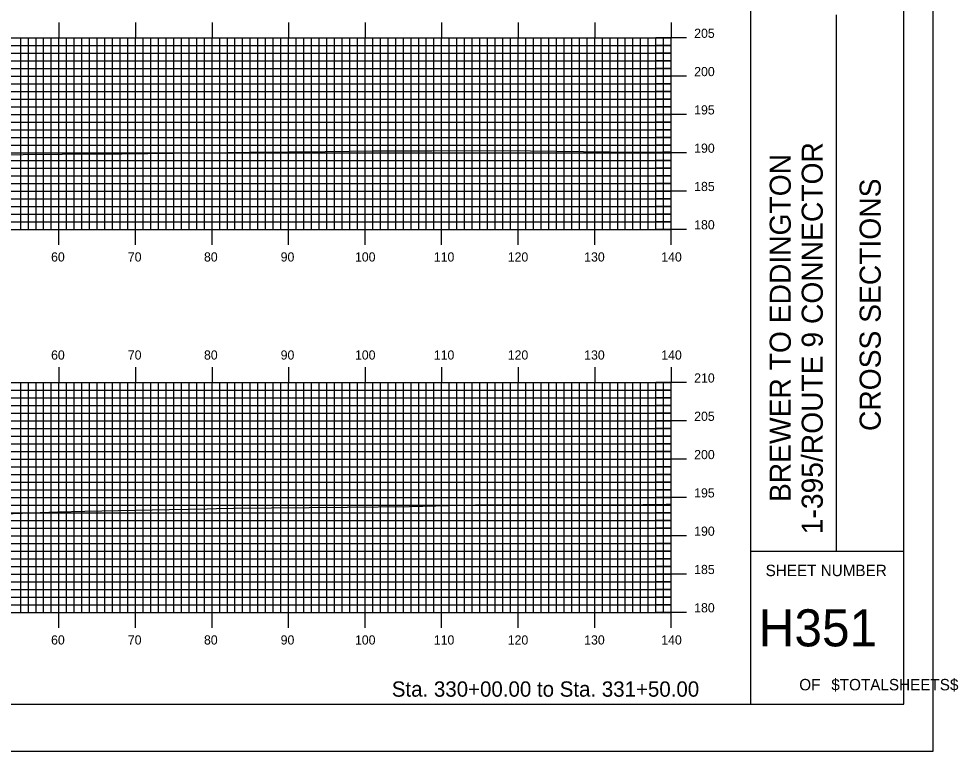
# Model space of a CAD drawing. Extents: x 1822392 to 1822735, y 442591 to 442811.
# Drawn here: x 1822612.5 to 1822735.3, y 442590.5 to 442686.2 of the extents above; entities that cross this region are included whole.
import ezdxf

# ---------------------------------------------------------------- set-up
doc = ezdxf.new("R2010")
doc.units = 0
for name, color, linetype in [('BORDER', 7, 'Continuous'), ('H_V ANNOTATION', 7, 'Continuous'), ('MAJOR', 7, 'Continuous'), ('MINOR', 7, 'Continuous'), ('PLOT BOUNDARY', 7, 'Continuous'), ('S_Roadway_Centerline', 7, 'Continuous')]:
    doc.layers.add(name, color=color, linetype=linetype)

msp = doc.modelspace()

# ---------------------------------------------------------------- linework, layer by layer
at = {"layer": 'BORDER'}
for p, q in [((1822708.17, 442596.67), (1822708.17, 442806.67)), ((1822719.35, 442616.67), (1822719.35, 442686.67)), ((1822708.17, 442616.67), (1822728.17, 442616.67))]:
    msp.add_line(p, q, dxfattribs=at)
msp.add_lwpolyline([(1822408.17, 442596.67), (1822728.17, 442596.67), (1822728.17, 442806.67), (1822408.17, 442806.67)], close=True, dxfattribs=at)
at = {"layer": 'MAJOR'}
for p, q in [((1822617.77, 442685.67), (1822617.77, 442683.67)), ((1822627.77, 442685.67), (1822627.77, 442683.67)), ((1822637.77, 442685.67), (1822637.77, 442683.67)), ((1822647.77, 442685.67), (1822647.77, 442683.67)), ((1822657.77, 442685.67), (1822657.77, 442683.67)), ((1822667.77, 442685.67), (1822667.77, 442683.67)), ((1822677.77, 442685.67), (1822677.77, 442683.67)), ((1822687.77, 442685.67), (1822687.77, 442683.67)), ((1822697.77, 442685.67), (1822697.77, 442683.67)), ((1822417.77, 442683.67), (1822697.77, 442683.67)), ((1822417.77, 442683.67), (1822697.77, 442683.67)), ((1822617.77, 442658.67), (1822617.77, 442683.67)), ((1822627.77, 442658.67), (1822627.77, 442683.67)), ((1822637.77, 442658.67), (1822637.77, 442683.67)), ((1822647.77, 442658.67), (1822647.77, 442683.67)), ((1822657.77, 442658.67), (1822657.77, 442683.67)), ((1822667.77, 442658.67), (1822667.77, 442683.67)), ((1822677.77, 442658.67), (1822677.77, 442683.67)), ((1822687.77, 442658.67), (1822687.77, 442683.67)), ((1822699.77, 442683.67), (1822695.77, 442683.67)), ((1822697.77, 442658.67), (1822697.77, 442683.67)), ((1822697.77, 442658.67), (1822697.77, 442683.67)), ((1822417.77, 442678.67), (1822697.77, 442678.67)), ((1822699.77, 442678.67), (1822695.77, 442678.67)), ((1822417.77, 442673.67), (1822697.77, 442673.67)), ((1822699.77, 442673.67), (1822695.77, 442673.67)), ((1822417.77, 442668.67), (1822697.77, 442668.67)), ((1822699.77, 442668.67), (1822695.77, 442668.67)), ((1822417.77, 442663.67), (1822697.77, 442663.67)), ((1822699.77, 442663.67), (1822695.77, 442663.67)), ((1822417.77, 442658.67), (1822697.77, 442658.67)), ((1822417.77, 442658.67), (1822697.77, 442658.67)), ((1822617.77, 442656.66), (1822617.77, 442658.67)), ((1822627.77, 442656.66), (1822627.77, 442658.67)), ((1822637.77, 442656.66), (1822637.77, 442658.67)), ((1822647.77, 442656.66), (1822647.77, 442658.67)), ((1822657.77, 442656.66), (1822657.77, 442658.67)), ((1822667.77, 442656.66), (1822667.77, 442658.67)), ((1822677.77, 442656.66), (1822677.77, 442658.67)), ((1822687.77, 442656.66), (1822687.77, 442658.67)), ((1822699.77, 442658.67), (1822695.77, 442658.67)), ((1822697.77, 442656.66), (1822697.77, 442658.67)), ((1822617.77, 442640.67), (1822617.77, 442638.67)), ((1822627.77, 442640.67), (1822627.77, 442638.67)), ((1822637.77, 442640.67), (1822637.77, 442638.67)), ((1822647.77, 442640.67), (1822647.77, 442638.67)), ((1822657.77, 442640.67), (1822657.77, 442638.67)), ((1822667.77, 442640.67), (1822667.77, 442638.67)), ((1822677.77, 442640.67), (1822677.77, 442638.67)), ((1822687.77, 442640.67), (1822687.77, 442638.67)), ((1822697.77, 442640.67), (1822697.77, 442638.67)), ((1822417.77, 442638.67), (1822697.77, 442638.67)), ((1822417.77, 442638.67), (1822697.77, 442638.67)), ((1822617.77, 442608.67), (1822617.77, 442638.67)), ((1822627.77, 442608.67), (1822627.77, 442638.67)), ((1822637.77, 442608.67), (1822637.77, 442638.67)), ((1822647.77, 442608.67), (1822647.77, 442638.67)), ((1822657.77, 442608.67), (1822657.77, 442638.67)), ((1822667.77, 442608.67), (1822667.77, 442638.67)), ((1822677.77, 442608.67), (1822677.77, 442638.67)), ((1822687.77, 442608.67), (1822687.77, 442638.67)), ((1822699.77, 442638.67), (1822695.77, 442638.67)), ((1822697.77, 442608.67), (1822697.77, 442638.67)), ((1822697.77, 442608.67), (1822697.77, 442638.67)), ((1822417.77, 442633.67), (1822697.77, 442633.67)), ((1822699.77, 442633.67), (1822695.77, 442633.67)), ((1822417.77, 442628.67), (1822697.77, 442628.67)), ((1822699.77, 442628.67), (1822695.77, 442628.67)), ((1822417.77, 442623.67), (1822697.77, 442623.67)), ((1822699.77, 442623.67), (1822695.77, 442623.67)), ((1822417.77, 442618.67), (1822697.77, 442618.67)), ((1822699.77, 442618.67), (1822695.77, 442618.67)), ((1822417.77, 442613.67), (1822697.77, 442613.67)), ((1822699.77, 442613.67), (1822695.77, 442613.67)), ((1822417.77, 442608.67), (1822697.77, 442608.67)), ((1822417.77, 442608.67), (1822697.77, 442608.67)), ((1822617.77, 442606.66), (1822617.77, 442608.67)), ((1822627.77, 442606.66), (1822627.77, 442608.67)), ((1822637.77, 442606.66), (1822637.77, 442608.67)), ((1822647.77, 442606.66), (1822647.77, 442608.67)), ((1822657.77, 442606.66), (1822657.77, 442608.67)), ((1822667.77, 442606.66), (1822667.77, 442608.67)), ((1822677.77, 442606.66), (1822677.77, 442608.67)), ((1822687.77, 442606.66), (1822687.77, 442608.67)), ((1822699.77, 442608.67), (1822695.77, 442608.67)), ((1822697.77, 442606.66), (1822697.77, 442608.67))]:
    msp.add_line(p, q, dxfattribs=at)
at = {"layer": 'MINOR'}
for p, q in [((1822612.77, 442658.67), (1822612.77, 442683.67)), ((1822613.77, 442658.67), (1822613.77, 442683.67)), ((1822614.77, 442658.67), (1822614.77, 442683.67)), ((1822615.77, 442658.67), (1822615.77, 442683.67)), ((1822616.77, 442658.67), (1822616.77, 442683.67)), ((1822618.77, 442658.67), (1822618.77, 442683.67)), ((1822619.77, 442658.67), (1822619.77, 442683.67)), ((1822620.77, 442658.67), (1822620.77, 442683.67)), ((1822621.77, 442658.67), (1822621.77, 442683.67)), ((1822622.77, 442658.67), (1822622.77, 442683.67)), ((1822623.77, 442658.67), (1822623.77, 442683.67)), ((1822624.77, 442658.67), (1822624.77, 442683.67)), ((1822625.77, 442658.67), (1822625.77, 442683.67)), ((1822626.77, 442658.67), (1822626.77, 442683.67)), ((1822628.77, 442658.67), (1822628.77, 442683.67)), ((1822629.77, 442658.67), (1822629.77, 442683.67)), ((1822630.77, 442658.67), (1822630.77, 442683.67)), ((1822631.77, 442658.67), (1822631.77, 442683.67)), ((1822632.77, 442658.67), (1822632.77, 442683.67)), ((1822633.77, 442658.67), (1822633.77, 442683.67)), ((1822634.77, 442658.67), (1822634.77, 442683.67)), ((1822635.77, 442658.67), (1822635.77, 442683.67)), ((1822636.77, 442658.67), (1822636.77, 442683.67)), ((1822638.77, 442658.67), (1822638.77, 442683.67)), ((1822639.77, 442658.67), (1822639.77, 442683.67)), ((1822640.77, 442658.67), (1822640.77, 442683.67)), ((1822641.77, 442658.67), (1822641.77, 442683.67)), ((1822642.77, 442658.67), (1822642.77, 442683.67)), ((1822643.77, 442658.67), (1822643.77, 442683.67)), ((1822644.77, 442658.67), (1822644.77, 442683.67)), ((1822645.77, 442658.67), (1822645.77, 442683.67)), ((1822646.77, 442658.67), (1822646.77, 442683.67)), ((1822648.77, 442658.67), (1822648.77, 442683.67)), ((1822649.77, 442658.67), (1822649.77, 442683.67)), ((1822650.77, 442658.67), (1822650.77, 442683.67)), ((1822651.77, 442658.67), (1822651.77, 442683.67)), ((1822652.77, 442658.67), (1822652.77, 442683.67)), ((1822653.77, 442658.67), (1822653.77, 442683.67)), ((1822654.77, 442658.67), (1822654.77, 442683.67)), ((1822655.77, 442658.67), (1822655.77, 442683.67)), ((1822656.77, 442658.67), (1822656.77, 442683.67)), ((1822658.77, 442658.67), (1822658.77, 442683.67)), ((1822659.77, 442658.67), (1822659.77, 442683.67)), ((1822660.77, 442658.67), (1822660.77, 442683.67)), ((1822661.77, 442658.67), (1822661.77, 442683.67)), ((1822662.77, 442658.67), (1822662.77, 442683.67)), ((1822663.77, 442658.67), (1822663.77, 442683.67)), ((1822664.77, 442658.67), (1822664.77, 442683.67)), ((1822665.77, 442658.67), (1822665.77, 442683.67)), ((1822666.77, 442658.67), (1822666.77, 442683.67)), ((1822668.77, 442658.67), (1822668.77, 442683.67)), ((1822669.77, 442658.67), (1822669.77, 442683.67)), ((1822670.77, 442658.67), (1822670.77, 442683.67)), ((1822671.77, 442658.67), (1822671.77, 442683.67)), ((1822672.77, 442658.67), (1822672.77, 442683.67)), ((1822673.77, 442658.67), (1822673.77, 442683.67)), ((1822674.77, 442658.67), (1822674.77, 442683.67)), ((1822675.77, 442658.67), (1822675.77, 442683.67)), ((1822676.77, 442658.67), (1822676.77, 442683.67)), ((1822678.77, 442658.67), (1822678.77, 442683.67)), ((1822679.77, 442658.67), (1822679.77, 442683.67)), ((1822680.77, 442658.67), (1822680.77, 442683.67)), ((1822681.77, 442658.67), (1822681.77, 442683.67)), ((1822682.77, 442658.67), (1822682.77, 442683.67)), ((1822683.77, 442658.67), (1822683.77, 442683.67)), ((1822684.77, 442658.67), (1822684.77, 442683.67)), ((1822685.77, 442658.67), (1822685.77, 442683.67)), ((1822686.77, 442658.67), (1822686.77, 442683.67)), ((1822688.77, 442658.67), (1822688.77, 442683.67)), ((1822689.77, 442658.67), (1822689.77, 442683.67)), ((1822690.77, 442658.67), (1822690.77, 442683.67)), ((1822691.77, 442658.67), (1822691.77, 442683.67)), ((1822692.77, 442658.67), (1822692.77, 442683.67)), ((1822693.77, 442658.67), (1822693.77, 442683.67)), ((1822694.77, 442658.67), (1822694.77, 442683.67)), ((1822695.77, 442658.67), (1822695.77, 442683.67)), ((1822696.77, 442658.67), (1822696.77, 442683.67)), ((1822417.77, 442682.67), (1822697.77, 442682.67)), ((1822417.77, 442681.67), (1822697.77, 442681.67)), ((1822697.77, 442682.67), (1822695.77, 442682.67)), ((1822697.77, 442681.67), (1822695.77, 442681.67)), ((1822417.77, 442680.67), (1822697.77, 442680.67)), ((1822697.77, 442680.67), (1822695.77, 442680.67)), ((1822417.77, 442679.67), (1822697.77, 442679.67)), ((1822697.77, 442679.67), (1822695.77, 442679.67)), ((1822417.77, 442677.67), (1822697.77, 442677.67)), ((1822417.77, 442676.67), (1822697.77, 442676.67)), ((1822697.77, 442677.67), (1822695.77, 442677.67)), ((1822697.77, 442676.67), (1822695.77, 442676.67)), ((1822417.77, 442675.67), (1822697.77, 442675.67)), ((1822697.77, 442675.67), (1822695.77, 442675.67)), ((1822417.77, 442674.67), (1822697.77, 442674.67)), ((1822697.77, 442674.67), (1822695.77, 442674.67)), ((1822417.77, 442672.67), (1822697.77, 442672.67)), ((1822697.77, 442672.67), (1822695.77, 442672.67)), ((1822417.77, 442671.67), (1822697.77, 442671.67)), ((1822417.77, 442670.67), (1822697.77, 442670.67)), ((1822697.77, 442671.67), (1822695.77, 442671.67)), ((1822697.77, 442670.67), (1822695.77, 442670.67)), ((1822417.77, 442669.67), (1822697.77, 442669.67)), ((1822697.77, 442669.67), (1822695.77, 442669.67)), ((1822417.77, 442667.67), (1822697.77, 442667.67)), ((1822697.77, 442667.67), (1822695.77, 442667.67)), ((1822417.77, 442666.67), (1822697.77, 442666.67)), ((1822417.77, 442665.67), (1822697.77, 442665.67)), ((1822697.77, 442666.67), (1822695.77, 442666.67)), ((1822697.77, 442665.67), (1822695.77, 442665.67)), ((1822417.77, 442664.67), (1822697.77, 442664.67)), ((1822697.77, 442664.67), (1822695.77, 442664.67)), ((1822417.77, 442662.67), (1822697.77, 442662.67)), ((1822697.77, 442662.67), (1822695.77, 442662.67)), ((1822417.77, 442661.67), (1822697.77, 442661.67)), ((1822417.77, 442660.67), (1822697.77, 442660.67)), ((1822697.77, 442661.67), (1822695.77, 442661.67)), ((1822697.77, 442660.67), (1822695.77, 442660.67)), ((1822417.77, 442659.67), (1822697.77, 442659.67)), ((1822697.77, 442659.67), (1822695.77, 442659.67)), ((1822612.77, 442608.67), (1822612.77, 442638.67)), ((1822613.77, 442608.67), (1822613.77, 442638.67)), ((1822614.77, 442608.67), (1822614.77, 442638.67)), ((1822615.77, 442608.67), (1822615.77, 442638.67)), ((1822616.77, 442608.67), (1822616.77, 442638.67)), ((1822618.77, 442608.67), (1822618.77, 442638.67)), ((1822619.77, 442608.67), (1822619.77, 442638.67)), ((1822620.77, 442608.67), (1822620.77, 442638.67)), ((1822621.77, 442608.67), (1822621.77, 442638.67)), ((1822622.77, 442608.67), (1822622.77, 442638.67)), ((1822623.77, 442608.67), (1822623.77, 442638.67)), ((1822624.77, 442608.67), (1822624.77, 442638.67)), ((1822625.77, 442608.67), (1822625.77, 442638.67)), ((1822626.77, 442608.67), (1822626.77, 442638.67)), ((1822628.77, 442608.67), (1822628.77, 442638.67)), ((1822629.77, 442608.67), (1822629.77, 442638.67)), ((1822630.77, 442608.67), (1822630.77, 442638.67)), ((1822631.77, 442608.67), (1822631.77, 442638.67)), ((1822632.77, 442608.67), (1822632.77, 442638.67)), ((1822633.77, 442608.67), (1822633.77, 442638.67)), ((1822634.77, 442608.67), (1822634.77, 442638.67)), ((1822635.77, 442608.67), (1822635.77, 442638.67)), ((1822636.77, 442608.67), (1822636.77, 442638.67)), ((1822638.77, 442608.67), (1822638.77, 442638.67)), ((1822639.77, 442608.67), (1822639.77, 442638.67)), ((1822640.77, 442608.67), (1822640.77, 442638.67)), ((1822641.77, 442608.67), (1822641.77, 442638.67)), ((1822642.77, 442608.67), (1822642.77, 442638.67)), ((1822643.77, 442608.67), (1822643.77, 442638.67)), ((1822644.77, 442608.67), (1822644.77, 442638.67)), ((1822645.77, 442608.67), (1822645.77, 442638.67)), ((1822646.77, 442608.67), (1822646.77, 442638.67)), ((1822648.77, 442608.67), (1822648.77, 442638.67)), ((1822649.77, 442608.67), (1822649.77, 442638.67)), ((1822650.77, 442608.67), (1822650.77, 442638.67)), ((1822651.77, 442608.67), (1822651.77, 442638.67)), ((1822652.77, 442608.67), (1822652.77, 442638.67)), ((1822653.77, 442608.67), (1822653.77, 442638.67)), ((1822654.77, 442608.67), (1822654.77, 442638.67)), ((1822655.77, 442608.67), (1822655.77, 442638.67)), ((1822656.77, 442608.67), (1822656.77, 442638.67)), ((1822658.77, 442608.67), (1822658.77, 442638.67)), ((1822659.77, 442608.67), (1822659.77, 442638.67)), ((1822660.77, 442608.67), (1822660.77, 442638.67)), ((1822661.77, 442608.67), (1822661.77, 442638.67)), ((1822662.77, 442608.67), (1822662.77, 442638.67)), ((1822663.77, 442608.67), (1822663.77, 442638.67)), ((1822664.77, 442608.67), (1822664.77, 442638.67)), ((1822665.77, 442608.67), (1822665.77, 442638.67)), ((1822666.77, 442608.67), (1822666.77, 442638.67)), ((1822668.77, 442608.67), (1822668.77, 442638.67)), ((1822669.77, 442608.67), (1822669.77, 442638.67)), ((1822670.77, 442608.67), (1822670.77, 442638.67)), ((1822671.77, 442608.67), (1822671.77, 442638.67)), ((1822672.77, 442608.67), (1822672.77, 442638.67)), ((1822673.77, 442608.67), (1822673.77, 442638.67)), ((1822674.77, 442608.67), (1822674.77, 442638.67)), ((1822675.77, 442608.67), (1822675.77, 442638.67)), ((1822676.77, 442608.67), (1822676.77, 442638.67)), ((1822678.77, 442608.67), (1822678.77, 442638.67)), ((1822679.77, 442608.67), (1822679.77, 442638.67)), ((1822680.77, 442608.67), (1822680.77, 442638.67)), ((1822681.77, 442608.67), (1822681.77, 442638.67)), ((1822682.77, 442608.67), (1822682.77, 442638.67)), ((1822683.77, 442608.67), (1822683.77, 442638.67)), ((1822684.77, 442608.67), (1822684.77, 442638.67)), ((1822685.77, 442608.67), (1822685.77, 442638.67)), ((1822686.77, 442608.67), (1822686.77, 442638.67)), ((1822688.77, 442608.67), (1822688.77, 442638.67)), ((1822689.77, 442608.67), (1822689.77, 442638.67)), ((1822690.77, 442608.67), (1822690.77, 442638.67)), ((1822691.77, 442608.67), (1822691.77, 442638.67)), ((1822692.77, 442608.67), (1822692.77, 442638.67)), ((1822693.77, 442608.67), (1822693.77, 442638.67)), ((1822694.77, 442608.67), (1822694.77, 442638.67)), ((1822695.77, 442608.67), (1822695.77, 442638.67)), ((1822696.77, 442608.67), (1822696.77, 442638.67)), ((1822417.77, 442637.67), (1822697.77, 442637.67)), ((1822697.77, 442637.67), (1822695.77, 442637.67)), ((1822417.77, 442636.67), (1822697.77, 442636.67)), ((1822697.77, 442636.67), (1822695.77, 442636.67)), ((1822417.77, 442635.67), (1822697.77, 442635.67)), ((1822697.77, 442635.67), (1822695.77, 442635.67)), ((1822417.77, 442634.67), (1822697.77, 442634.67)), ((1822697.77, 442634.67), (1822695.77, 442634.67)), ((1822417.77, 442632.67), (1822697.77, 442632.67)), ((1822697.77, 442632.67), (1822695.77, 442632.67)), ((1822417.77, 442631.67), (1822697.77, 442631.67)), ((1822697.77, 442631.67), (1822695.77, 442631.67)), ((1822417.77, 442630.67), (1822697.77, 442630.67)), ((1822697.77, 442630.67), (1822695.77, 442630.67)), ((1822417.77, 442629.67), (1822697.77, 442629.67)), ((1822697.77, 442629.67), (1822695.77, 442629.67)), ((1822417.77, 442627.67), (1822697.77, 442627.67)), ((1822697.77, 442627.67), (1822695.77, 442627.67)), ((1822417.77, 442626.67), (1822697.77, 442626.67)), ((1822697.77, 442626.67), (1822695.77, 442626.67)), ((1822417.77, 442625.67), (1822697.77, 442625.67)), ((1822697.77, 442625.67), (1822695.77, 442625.67)), ((1822417.77, 442624.67), (1822697.77, 442624.67)), ((1822697.77, 442624.67), (1822695.77, 442624.67)), ((1822417.77, 442622.67), (1822697.77, 442622.67)), ((1822697.77, 442622.67), (1822695.77, 442622.67)), ((1822417.77, 442621.67), (1822697.77, 442621.67)), ((1822697.77, 442621.67), (1822695.77, 442621.67)), ((1822417.77, 442620.67), (1822697.77, 442620.67)), ((1822697.77, 442620.67), (1822695.77, 442620.67)), ((1822417.77, 442619.67), (1822697.77, 442619.67)), ((1822697.77, 442619.67), (1822695.77, 442619.67)), ((1822417.77, 442617.67), (1822697.77, 442617.67)), ((1822417.77, 442616.67), (1822697.77, 442616.67)), ((1822697.77, 442617.67), (1822695.77, 442617.67)), ((1822697.77, 442616.67), (1822695.77, 442616.67)), ((1822417.77, 442615.67), (1822697.77, 442615.67)), ((1822697.77, 442615.67), (1822695.77, 442615.67)), ((1822417.77, 442614.67), (1822697.77, 442614.67)), ((1822697.77, 442614.67), (1822695.77, 442614.67)), ((1822417.77, 442612.67), (1822697.77, 442612.67)), ((1822417.77, 442611.67), (1822697.77, 442611.67)), ((1822697.77, 442612.67), (1822695.77, 442612.67)), ((1822697.77, 442611.67), (1822695.77, 442611.67)), ((1822417.77, 442610.67), (1822697.77, 442610.67)), ((1822697.77, 442610.67), (1822695.77, 442610.67)), ((1822417.77, 442609.67), (1822697.77, 442609.67)), ((1822697.77, 442609.67), (1822695.77, 442609.67))]:
    msp.add_line(p, q, dxfattribs=at)
at = {"layer": 'PLOT BOUNDARY'}
msp.add_lwpolyline([(1822391.98, 442590.55), (1822731.98, 442590.55), (1822731.98, 442810.55), (1822391.98, 442810.55)], close=True, dxfattribs=at)
at = {"layer": 'S_Roadway_Centerline'}
for points in [[(1822607.93, 442668.4), (1822623.32, 442668.51), (1822624.98, 442668.51), (1822625.99, 442668.51), (1822629.39, 442668.56), (1822639.75, 442668.71), (1822642.75, 442668.75), (1822652.55, 442668.83), (1822658.82, 442668.94), (1822666.47, 442668.94), (1822675.88, 442668.95), (1822693.25, 442668.73), (1822694.24, 442668.74), (1822695.44, 442668.76), (1822697.77, 442668.83)], [(1822604.77, 442621.3), (1822617.64, 442621.79), (1822621.17, 442621.87), (1822632.18, 442622.12), (1822637.14, 442622.2), (1822638.35, 442622.25), (1822640.57, 442622.29), (1822655.41, 442622.41), (1822663.57, 442622.48), (1822672.2, 442622.7), (1822686.81, 442622.69), (1822689.41, 442622.72), (1822691.08, 442622.71), (1822697.09, 442622.78), (1822697.77, 442622.79)]]:
    msp.add_lwpolyline(points, dxfattribs=at)

# ---------------------------------------------------------------- texts
at = {"layer": 'BORDER'}
for s, p in [('1-395/ROUTE 9 CONNECTOR', (1822717.57, 442618.87)), ('BREWER TO EDDINGTON', (1822713.39, 442623.07)), ('CROSS SECTIONS', (1822725.14, 442632.34))]:
    msp.add_text(s, height=2.7557, rotation=90, dxfattribs=at).set_placement(p)
for s, height, p in [('SHEET NUMBER', 1.4905, (1822710.1, 442613.4)), ('H351', 4.839, (1822709.2, 442604.23)), ('OF', 1.491, (1822714.5, 442598.49)), ('$TOTALSHEETS$', 1.4905, (1822718.68, 442598.49))]:
    msp.add_text(s, height=height, dxfattribs=at).set_placement(p)
at = {"layer": 'H_V ANNOTATION'}
for s, height, p in [('205', 1.2, (1822700.77, 442683.67)), ('200', 1.2, (1822700.77, 442678.67)), ('195', 1.2, (1822700.77, 442673.67)), ('190', 1.2, (1822700.77, 442668.67)), ('185', 1.2, (1822700.77, 442663.67)), ('180', 1.2, (1822700.77, 442658.67)), ('60', 1.2, (1822616.74, 442654.47)), ('70', 1.2, (1822626.77, 442654.47)), ('80', 1.2, (1822636.72, 442654.47)), ('90', 1.2, (1822646.74, 442654.47)), ('100', 1.2, (1822656.45, 442654.47)), ('110', 1.2, (1822666.75, 442654.47)), ('120', 1.2, (1822676.41, 442654.47)), ('130', 1.2, (1822686.4, 442654.47)), ('140', 1.2, (1822696.47, 442654.47)), ('60', 1.2, (1822616.74, 442641.67)), ('70', 1.2, (1822626.77, 442641.67)), ('80', 1.2, (1822636.72, 442641.67)), ('90', 1.2, (1822646.74, 442641.67)), ('100', 1.2, (1822656.45, 442641.67)), ('110', 1.2, (1822666.75, 442641.67)), ('120', 1.2, (1822676.41, 442641.67)), ('130', 1.2, (1822686.4, 442641.67)), ('140', 1.2, (1822696.47, 442641.67)), ('210', 1.2, (1822700.77, 442638.67)), ('205', 1.2, (1822700.77, 442633.67)), ('200', 1.2, (1822700.77, 442628.67)), ('195', 1.2, (1822700.77, 442623.67)), ('190', 1.2, (1822700.77, 442618.67)), ('185', 1.2, (1822700.77, 442613.67)), ('180', 1.2, (1822700.77, 442608.67)), ('60', 1.2, (1822616.74, 442604.47)), ('70', 1.2, (1822626.77, 442604.47)), ('80', 1.2, (1822636.72, 442604.47)), ('90', 1.2, (1822646.74, 442604.47)), ('100', 1.2, (1822656.45, 442604.47)), ('110', 1.2, (1822666.75, 442604.47)), ('120', 1.2, (1822676.41, 442604.47)), ('130', 1.2, (1822686.4, 442604.47)), ('140', 1.2, (1822696.47, 442604.47)), ('Sta. 330+00.00 to Sta. 331+50.00', 2.0004, (1822661.26, 442597.66))]:
    msp.add_text(s, height=height, dxfattribs=at).set_placement(p)

doc.saveas('drawing.dxf')
